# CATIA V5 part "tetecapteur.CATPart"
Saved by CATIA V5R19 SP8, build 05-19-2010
Part number: tetecapteur
Revision: ANY
Definition: UNKNOWN
Nomenclature: tetecapteur
Source: Unknown
Bounding box of the stored display mesh (mm): x -0.3 to 13, y -2.53 to 2.53, z 0 to 1.9
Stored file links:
  D:\Documents\1_Travail\1 - ac-limoges.fr\ac-limoges.fr\Emmanuel Maynard - STI2D_Turgot\2 -2I2D\2_SEQUENCE_Serrure_Biométrique\5-Spé_ITEC\Serrure_Bio_Eleve\tetecapteur.CATPart
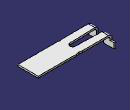
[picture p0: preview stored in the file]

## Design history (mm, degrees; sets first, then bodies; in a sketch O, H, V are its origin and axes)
Body1 "Enlèv. mat.-Extru.2" (main body)
  Solid1: solid without history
